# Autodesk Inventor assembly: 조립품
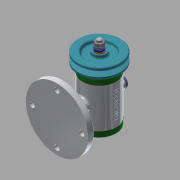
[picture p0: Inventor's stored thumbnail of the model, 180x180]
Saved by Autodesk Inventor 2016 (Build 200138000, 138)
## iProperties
Created: 2018-12
Part Number: 조립품
Material: 일반
Document SubType Name: Assembly
Designer: 605-08
Author: 605-08
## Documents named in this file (15)
- C:\Users\605-08\Desktop\481208V1007\조립품.iam
- C:\Users\605-08\Desktop\481208V1007\본체.ipt
- C:\Users\605-08\Desktop\481208V1007\뒤커버.ipt
- C:\Users\605-08\Desktop\481208V1007\베어링 15 x 32 x 9.ipt
- C:\Users\605-08\Desktop\481208V1007\앞커버.ipt
- C:\Users\605-08\Desktop\481208V1007\오일 실 15 25 7.ipt
- C:\Users\605-08\Desktop\481208V1007\볼트 M4 x 12.ipt
- C:\Users\605-08\Desktop\481208V1007\V벨트풀리.ipt
- C:\Users\605-08\Desktop\481208V1007\축.ipt
- C:\Users\605-08\Desktop\481208V1007\키 3 x 3 x 12.ipt
- C:\Users\605-08\Desktop\481208V1007\너트 M8.ipt
- 너트 M8.ipt
- C:\Users\605-08\Desktop\481208V1007\스프링와셔 8.ipt
- C:\Users\605-08\Desktop\481208V1007\와셔 8x17.ipt
- C:\Users\605-08\Desktop\481208V1007\고무캡.ipt
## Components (2 placed, 2 different names)
1. V벨트풀리:1
2. 고무캡:1
